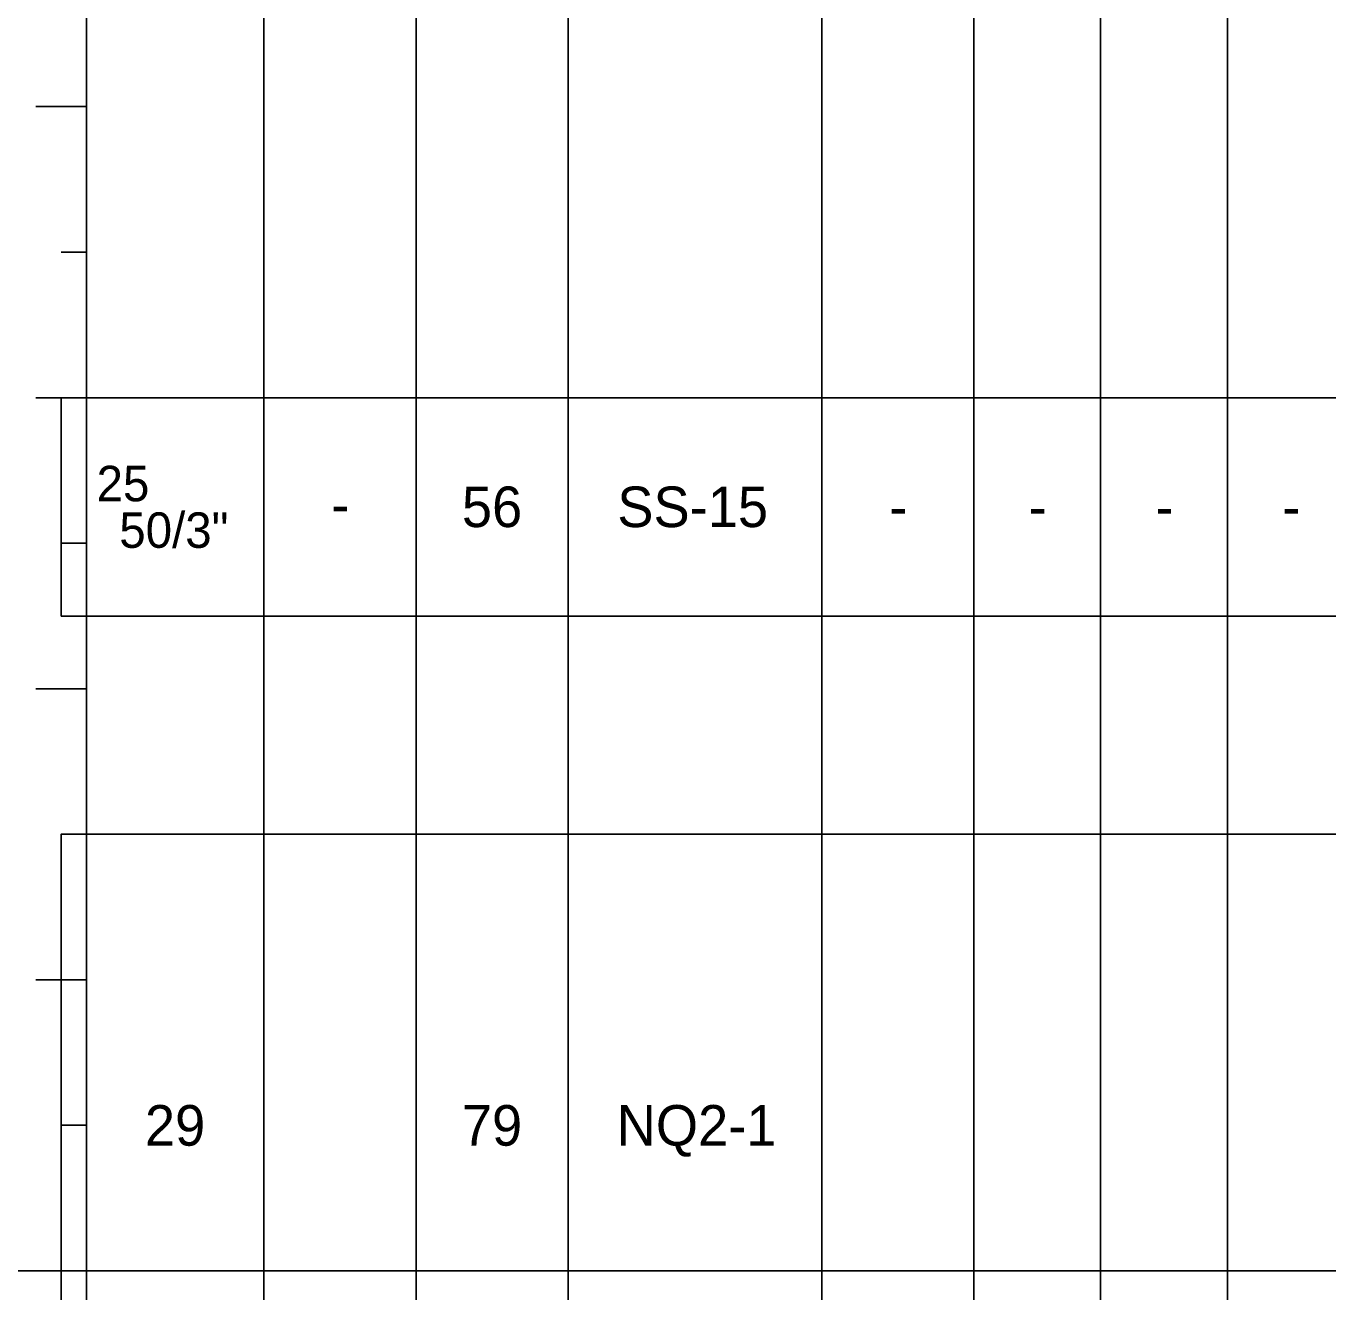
# Model space of a CAD drawing. Extents: x 0 to 0.83, y -0.65 to 1.27.
# Drawn here: x 0.4026 to 0.6165, y -0.0035 to 0.2046 of the extents above; entities that cross this region are included whole.
import ezdxf

# ---------------------------------------------------------------- set-up
doc = ezdxf.new("R2010")
doc.units = 0

msp = doc.modelspace()

# ---------------------------------------------------------------- linework, layer by layer
for points in [[(0, 0), (0.83333, 0), (0.83333, 1.275), (0, 1.275)], [(0, 0), (0.83333, 0), (0.83333, 1.275), (0, 1.275)], [(0, 0), (0.83333, 0), (0.83333, 1.275), (0, 1.275)], [(0, 0), (0.83333, 0), (0.83333, 1.275), (0, 1.275)], [(0, 0), (0.83333, 0), (0.83333, 1.275), (0, 1.275)], [(0.40833, 0.10762), (0.4125, 0.10762), (0.4125, 0.1435), (0.40833, 0.1435)], [(0.40833, -0.02392), (0.4125, -0.02392), (0.4125, 0.07175), (0.40833, 0.07175)]]:
    msp.add_lwpolyline(points, close=True)
for points in [[(0.4125, 1.22083), (0.4125, -0.64575)], [(0.4125, 1.22083), (0.4125, -0.64575)], [(0.44167, 1.22083), (0.44167, -0.64575)], [(0.46667, 1.22083), (0.46667, -0.64575)], [(0.49167, 1.22083), (0.49167, -0.64575)], [(0.53333, 1.22083), (0.53333, -0.64575)], [(0.55833, 1.22083), (0.55833, -0.64575)], [(0.57917, 1.20833), (0.57917, -0.64575)], [(0.6, 1.20833), (0.6, -0.64575)], [(0.4125, 0.19133), (0.40417, 0.19133)], [(0.4125, 0.19133), (0.40833, 0.19133)], [(0.4125, 0.16742), (0.40833, 0.16742)], [(0.4125, 0.1435), (0.40417, 0.1435)], [(0.40833, 0.1435), (0.40833, 0.10762)], [(0.40833, 0.1435), (0.4125, 0.1435)], [(0.4125, 0.1435), (0.40833, 0.1435)], [(0.4125, 0.1435), (0.44167, 0.1435)], [(0.44167, 0.1435), (0.46667, 0.1435)], [(0.46667, 0.1435), (0.49167, 0.1435)], [(0.49167, 0.1435), (0.53333, 0.1435)], [(0.53333, 0.1435), (0.55833, 0.1435)], [(0.55833, 0.1435), (0.57917, 0.1435)], [(0.57917, 0.1435), (0.6, 0.1435)], [(0.6, 0.1435), (0.62083, 0.1435)], [(0.4125, 0.11958), (0.40833, 0.11958)], [(0.40833, 0.10762), (0.4125, 0.10762)], [(0.4125, 0.10762), (0.44167, 0.10762)], [(0.44167, 0.10762), (0.46667, 0.10762)], [(0.46667, 0.10762), (0.49167, 0.10762)], [(0.49167, 0.10762), (0.53333, 0.10762)], [(0.53333, 0.10762), (0.55833, 0.10762)], [(0.55833, 0.10762), (0.57917, 0.10762)], [(0.57917, 0.10762), (0.6, 0.10762)], [(0.6, 0.10762), (0.62083, 0.10762)], [(0.4125, 0.09567), (0.40417, 0.09567)], [(0.4125, 0.09567), (0.40833, 0.09567)], [(0.40833, 0.07175), (0.40833, -0.02392)], [(0.40833, 0.07175), (0.4125, 0.07175)], [(0.4125, 0.07175), (0.40833, 0.07175)], [(0.4125, 0.07175), (0.44167, 0.07175)], [(0.44167, 0.07175), (0.46667, 0.07175)], [(0.46667, 0.07175), (0.49167, 0.07175)], [(0.49167, 0.07175), (0.53333, 0.07175)], [(0.53333, 0.07175), (0.55833, 0.07175)], [(0.55833, 0.07175), (0.57917, 0.07175)], [(0.57917, 0.07175), (0.6, 0.07175)], [(0.6, 0.07175), (0.62083, 0.07175)], [(0.4125, 0.04783), (0.40417, 0.04783)], [(0.4125, 0.04783), (0.40833, 0.04783)], [(0.4125, 0.02392), (0.40833, 0.02392)], [(0, 0), (0.83333, 0)], [(0.4125, 0), (0.40417, 0)], [(0.4125, 0), (0.40833, 0)]]:
    msp.add_lwpolyline(points)

# ---------------------------------------------------------------- texts
for s, height, p in [('25', 0.005833, (0.41417, 0.12647)), ('56', 0.006667, (0.4742, 0.12223)), ('SS-15', 0.006667, (0.49974, 0.12223)), ('50/3"', 0.005833, (0.4179, 0.11882)), ('-', 0.00667, (0.45276, 0.12265)), ('-', 0.00667, (0.54443, 0.12223)), ('-', 0.00667, (0.56734, 0.12223)), ('-', 0.00667, (0.58818, 0.12223)), ('-', 0.00667, (0.60901, 0.12223)), ('29', 0.006667, (0.42211, 0.02058)), ('79', 0.006667, (0.47419, 0.02058)), ('NQ2-1', 0.006667, (0.49964, 0.02058))]:
    msp.add_text(s, height=height).set_placement(p)

doc.saveas('drawing.dxf')
